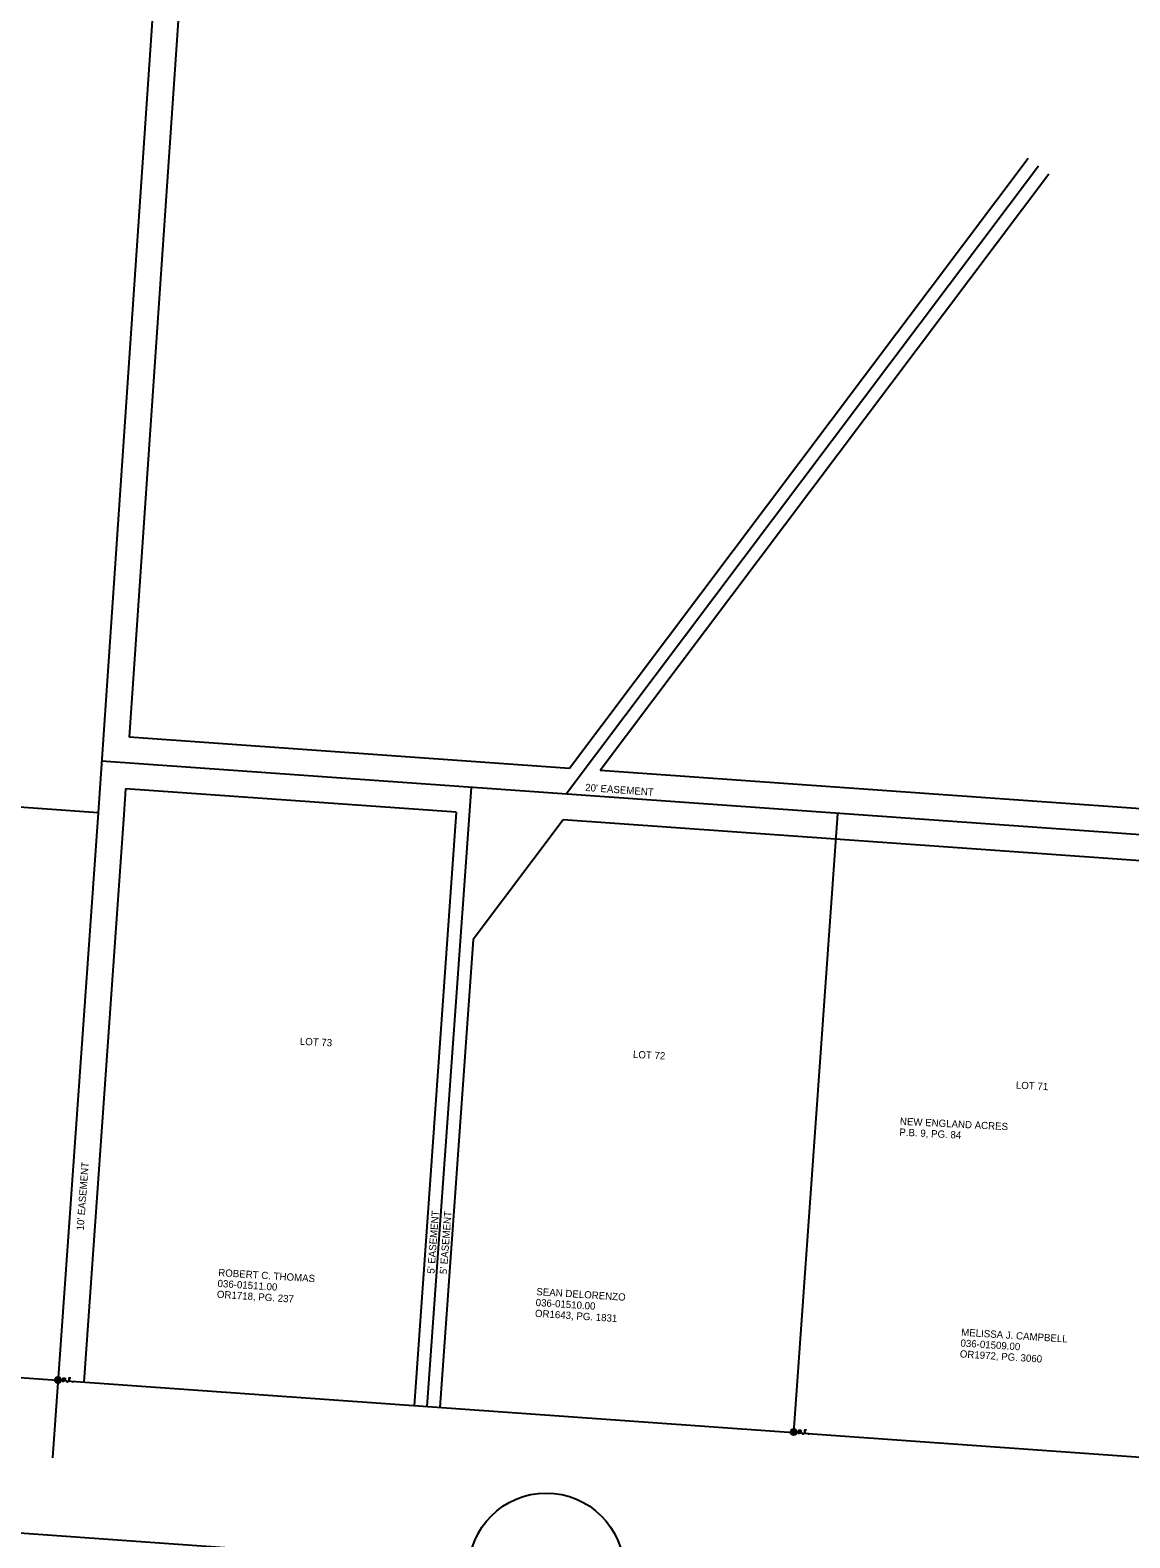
# Model space of a CAD drawing. Extents: x 1898254 to 1901377, y 701554 to 704886.
# Drawn here: x 1898968 to 1899393, y 703259 to 703841 of the extents above; entities that cross this region are included whole.
import ezdxf

# ---------------------------------------------------------------- set-up
doc = ezdxf.new("R2010")
doc.units = 0
for name, color, linetype in [('DV_X_Property_Line', 7, 'Continuous'), ('DV_X_Text', 7, 'Continuous'), ('RW_X_Esmt_General', 7, 'Continuous'), ('RW_X_Esmt_U', 7, 'Continuous'), ('RW_X_Fee_RW', 7, 'Continuous'), ('SC_Scratch1', 7, 'Continuous'), ('SC_Scratch2', 7, 'Continuous'), ('SV_X_Mon_Cells_Found', 7, 'Continuous')]:
    doc.layers.add(name, color=color, linetype=linetype)

msp = doc.modelspace()

# ---------------------------------------------------------------- linework, layer by layer
at = {"layer": 'DV_X_Property_Line'}
for p, q in [((1899357.75, 703788.77), (1899175.29, 703546.06)), ((1898994.39, 703538.88), (1898645.43, 703563.69)), ((1899563.1, 703518.49), (1898995.75, 703558.83)), ((1899138.49, 703548.68), (1899121.47, 703309.29)), ((1898994.39, 703538.88), (1898976.73, 703289.5)), ((1899280.14, 703538.61), (1899263.11, 703299.21))]:
    msp.add_line(p, q, dxfattribs=at)
at = {"layer": 'DV_X_Text'}
msp.add_line((1899086.29, 704885.75), (1898994.39, 703538.88), dxfattribs=at)
at = {"layer": 'RW_X_Esmt_General'}
msp.add_line((1899139.33, 703489.9), (1899126.46, 703308.93), dxfattribs=at)
at = {"layer": 'RW_X_Esmt_U'}
for p, q in [((1899096.27, 704885.07), (1899006.4, 703568.1)), ((1899353.75, 703791.78), (1899176.51, 703556)), ((1899361.75, 703785.77), (1899188.39, 703555.16)), ((1899176.51, 703556), (1899006.4, 703568.1)), ((1899563.81, 703528.46), (1899188.39, 703555.16)), ((1899005.04, 703548.15), (1899004.36, 703538.19)), ((1899132.8, 703539.06), (1899005.04, 703548.15)), ((1899004.36, 703538.19), (1898988.83, 703318.72)), ((1899132.8, 703539.06), (1899116.48, 703309.64)), ((1899174.08, 703536.13), (1899139.33, 703489.9)), ((1899562.39, 703508.51), (1899174.08, 703536.13))]:
    msp.add_line(p, q, dxfattribs=at)
at = {"layer": 'RW_X_Fee_RW'}
for p, q in [((1898630.14, 703344.22), (1899526.13, 703280.51)), ((1899763.77, 703203.46), (1898449.4, 703296.93))]:
    msp.add_line(p, q, dxfattribs=at)
at = {"layer": 'SC_Scratch1'}
msp.add_circle((1899167.56, 703245.86), 30, dxfattribs=at)
at = {"layer": 'SC_Scratch2'}
msp.add_circle((1899815.76, 703229.84), 1561.35, dxfattribs=at)
at = {"layer": 'SV_X_Mon_Cells_Found'}
for points in [[(1898980.86, 703318.73), (1898980.86, 703320.33), (1898981.39, 703320.33), (1898981.44, 703320.32), (1898981.52, 703320.29), (1898981.55, 703320.27), (1898981.58, 703320.24), (1898981.63, 703320.18), (1898981.66, 703320.12), (1898981.68, 703320.02), (1898981.68, 703319.87), (1898981.67, 703319.82), (1898981.65, 703319.74), (1898981.61, 703319.65), (1898981.56, 703319.61), (1898981.53, 703319.59), (1898981.47, 703319.56), (1898981.39, 703319.55), (1898980.86, 703319.55)], [(1898983.87, 703320.33), (1898983.11, 703320.33), (1898983.11, 703318.73)], [(1898983.11, 703319.55), (1898983.65, 703319.55)], [(1898982.5, 703318.95), (1898982.56, 703318.95), (1898982.59, 703318.92), (1898982.62, 703318.87), (1898982.62, 703318.81), (1898982.59, 703318.76), (1898982.56, 703318.73), (1898982.5, 703318.73), (1898982.47, 703318.76), (1898982.43, 703318.81), (1898982.43, 703318.87), (1898982.47, 703318.92), (1898982.5, 703318.95)], [(1898984.65, 703318.95), (1898984.7, 703318.95), (1898984.74, 703318.92), (1898984.77, 703318.87), (1898984.77, 703318.81), (1898984.74, 703318.76), (1898984.7, 703318.73), (1898984.65, 703318.73), (1898984.62, 703318.76), (1898984.58, 703318.81), (1898984.58, 703318.87), (1898984.62, 703318.92), (1898984.65, 703318.95)], [(1899265.12, 703298.62), (1899265.12, 703300.22), (1899265.65, 703300.22), (1899265.71, 703300.2), (1899265.79, 703300.18), (1899265.82, 703300.15), (1899265.85, 703300.13), (1899265.9, 703300.07), (1899265.93, 703300), (1899265.95, 703299.9), (1899265.95, 703299.75), (1899265.94, 703299.7), (1899265.92, 703299.62), (1899265.87, 703299.54), (1899265.83, 703299.5), (1899265.8, 703299.47), (1899265.74, 703299.45), (1899265.65, 703299.44), (1899265.12, 703299.44)], [(1899266.77, 703298.83), (1899266.82, 703298.83), (1899266.85, 703298.81), (1899266.89, 703298.76), (1899266.89, 703298.69), (1899266.85, 703298.64), (1899266.82, 703298.62), (1899266.77, 703298.62), (1899266.73, 703298.64), (1899266.7, 703298.69), (1899266.7, 703298.76), (1899266.73, 703298.81), (1899266.77, 703298.83)], [(1899268.13, 703300.22), (1899267.37, 703300.22), (1899267.37, 703298.62)], [(1899267.37, 703299.44), (1899267.91, 703299.44)], [(1899268.92, 703298.83), (1899268.97, 703298.83), (1899269, 703298.81), (1899269.04, 703298.76), (1899269.04, 703298.69), (1899269, 703298.64), (1899268.97, 703298.62), (1899268.92, 703298.62), (1899268.88, 703298.64), (1899268.85, 703298.69), (1899268.85, 703298.76), (1899268.88, 703298.81), (1899268.92, 703298.83)]]:
    msp.add_lwpolyline(points, dxfattribs=at)
for centre, radius in [((1898978.86, 703319.53), 1.2), ((1898978.86, 703319.53), 0.495), ((1899263.13, 703299.42), 1.2), ((1899263.13, 703299.42), 0.495)]:
    msp.add_circle(centre, radius, dxfattribs=at)

# ---------------------------------------------------------------- texts
at = {"layer": 'DV_X_Text'}
for s, rotation, p in [("20' EASEMENT ", 355.93252, (1899182.53, 703547.3)), ('LOT 73', 357.09486, (1899072.29, 703449.16)), ('LOT 72', 357.09486, (1899201.01, 703444.09)), ('LOT 71', 357.09486, (1899348.95, 703432.21)), ('NEW ENGLAND ACRES', 357.09486, (1899304.14, 703418.24)), ('P.B. 9, PG. 84', 357.09486, (1899303.93, 703414.05)), ("10' EASEMENT ", 85.7139, (1898988.83, 703377.29)), ("5' EASEMENT ", 85.7139, (1899124.31, 703360.6)), ("5' EASEMENT ", 85.7139, (1899129.14, 703360.4)), ('ROBERT C. THOMAS', 356.3351, (1899040.76, 703359.75)), ('036-01511.00', 356.3351, (1899040.49, 703355.55)), ('SEAN DELORENZO', 356.3351, (1899163.66, 703352.39)), ('OR1718, PG. 237', 356.3351, (1899040.23, 703351.36)), ('036-01510.00', 356.3351, (1899163.4, 703348.19)), ('OR1643, PG. 1831', 356.3351, (1899163.13, 703344)), ('MELISSA J. CAMPBELL', 356.3351, (1899327.81, 703336.69)), ('036-01509.00', 356.3351, (1899327.54, 703332.5)), ('OR1972, PG. 3060', 356.3351, (1899327.27, 703328.31))]:
    msp.add_text(s, height=2.8, rotation=rotation, dxfattribs=at).set_placement(p)

doc.saveas('drawing.dxf')
